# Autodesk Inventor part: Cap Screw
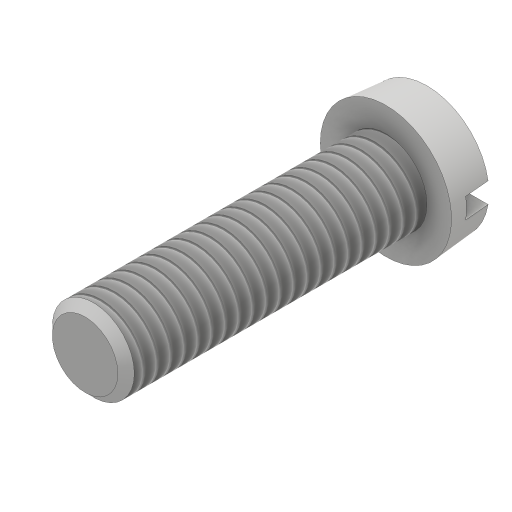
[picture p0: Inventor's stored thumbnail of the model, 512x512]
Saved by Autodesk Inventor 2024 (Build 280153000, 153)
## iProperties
Created: 2016-05
Part Number: Cap Screw
Material: Generic
Document SubType Name: Modeling
Designer: CADCIM
Density: 1 g/cm^3
Appearance: Default
Author: CADCIM
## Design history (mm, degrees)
sketch "Sketch2"
  geometry: C1 r 4.8 at (0, 0); 1 further point
  constraints: 1 centre point, 1 coincident
  dimensions: "d0" = 9.6 diameter of C1
extrude "Extrusion1" new body sketch "Sketch2" distance "d1" = 3; taper "d2" = -5 deg
sketch "Sketch3"
  geometry: C1 r 3 at (0, 0); 1 further point
  constraints: 1 centre point, 1 coincident
  dimensions: "d3" = 6 diameter of C1
extrude "Extrusion2" join sketch "Sketch3" distance "d4" = 22; taper "d5" = 0 deg
sketch "Sketch4"
  geometry: L1 (-13.358, -0.75)-(13.048, -0.75); L2 (13.048, -0.75)-(13.048, 0.75); L3 (13.048, 0.75)-(-13.358, 0.75); L4 (-13.358, 0.75)-(-13.358, -0.75); L5 (0, 0)-(-15.613, 0)
  constraints: 10 end point, 3 parallel, 1 horizontal, 1 perpendicular, 1 other
  dimensions: "d6" = 1.5 distance of L3.end L1.start
extrude "Extrusion3" cut sketch "Sketch4" distance "d7" = 1.8; taper "d8" = 0 deg
thread "Thread1" dims "d9" = 10, "d10" = 0
chamfer "Chamfer1" distance "d11" = 0.6; stored, may be unused: second distance "d12" = 2, angle "d13" = 45 deg
body "Solid1"
